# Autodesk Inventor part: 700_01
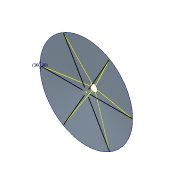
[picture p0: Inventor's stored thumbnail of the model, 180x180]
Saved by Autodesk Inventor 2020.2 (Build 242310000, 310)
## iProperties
Created: 2017-03
Part Number: 700_01
Material: Stal
Document SubType Name: Modeling
Designer: F.Stasiak
Density: 7.85 g/cm^3
Appearance: Stalowoniebieska
Mass: 932325 g
Surface Area: 396909 cm^2
Volume: 118768 cm^3
Catalog Web Link: www.expertbooks.pl
Manager: www.cadconsulting.pl
Company: Fabian Stasiak CAD Consulting
Author: F.Stasiak
Subject: Zbiór ćwiczeń. Autodesk Inventor 2020. Kurs Professional
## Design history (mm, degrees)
sketch "Szkic1"
  geometry: L1 (0, 0)-(0, 400); L2 (-2500, 0)-(0, 0); L3 (0, 400)-(-200, 400); L4 (-200, 400)-(-2500, 0)
  constraints: 8 end point, 1 horizontal, 1 perpendicular, 1 vertical
  dimensions: "d0" = 400 distance of L1.start L1.end; "d1" = 5000 diameter of L2.start L1; "d2" = 400 vertical distance of L3.end L1
feature "PowObrotowa1" sketch "Szkic1" dims angle "d3" = 90 deg
feature "Pogrubienie1" dims "d4" = 6, "d5" = 6
sketch "Szkic2"
  geometry: L1 (2500, 0)-(200, 0); L2 (1250, 2165.064)-(100, 173.205); L3 (-1250, 2165.064)-(-100, 173.205); L4 (-2500, 0)-(-200, 0); L5 (-1250, -2165.064)-(-100, -173.205); L6 (1250, -2165.064)-(100, -173.205); 3 further points
  constraints: 12 end point, 2 horizontal alignment, 1 horizontal, 21 other
  dimensions: "d8" = 360 deg dimension on point (0, 0) L1.start (derived)
sketch "Szkic 3D1"
  node "Rzutuj na powierzchnię1"
node "Bryła1"
body "Srf1"
